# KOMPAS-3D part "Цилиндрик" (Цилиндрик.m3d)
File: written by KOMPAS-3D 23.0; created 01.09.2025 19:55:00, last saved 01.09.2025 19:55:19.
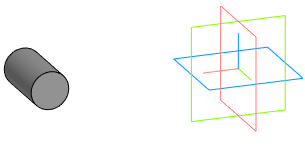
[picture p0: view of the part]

Document properties: Автор: Inspektor_Kot; Полное имя файла: I:\Autodesk Inventor Projects\ИМ-ИТ ЦД\Вариант 3\Цилиндрик.m3d

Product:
- Part/product: Цилиндрик
    Масса: 0.093785

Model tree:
1. Эскиз:1  (with: Элемент выдавливания:2)
2. Элемент выдавливания:1  (with: Элемент выдавливания:4)
     Расстояние 1 = -38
